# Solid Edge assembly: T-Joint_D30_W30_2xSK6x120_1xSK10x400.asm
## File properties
Author: fknapp
Template: iso metric assembly.asm
Last saved by: fknapp
Revision: 9
Application: Solid Edge
Username: fknapp
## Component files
T-Joint_D30_W30.par
SK Schraube 6x120_ohne_Gewinde.par
SK Schraube 10x400_ohne_Gewinde_22042020.par
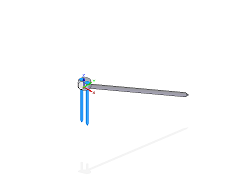
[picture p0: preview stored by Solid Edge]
